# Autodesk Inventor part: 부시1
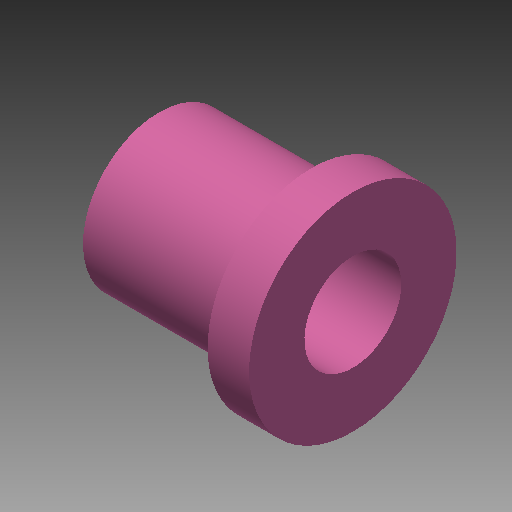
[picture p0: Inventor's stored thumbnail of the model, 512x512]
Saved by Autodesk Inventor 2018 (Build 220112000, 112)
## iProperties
Created: 2020-03
Part Number: 부시1
Material: 스테인리스강
Document SubType Name: Modeling
Designer: mduedu
Density: 8.08 g/cm^3
Appearance: 분홍색
Mass: 8.37674 g
Surface Area: 11.0584 cm^2
Volume: 1.03673 cm^3
Author: mduedu
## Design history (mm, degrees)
sketch "스케치1"
  geometry: L1 (0, 0)-(11, 0); L2 (11, 0)-(11, 5.5); L3 (11, 5.5)-(0, 5.5); L4 (0, 5.5)-(0, 0); L5 (11, 0)-(14, 0); L6 (14, 0)-(14, 7.5); L7 (14, 7.5)-(11, 7.5); L8 (11, 7.5)-(11, 0)
  constraints: 16 end point, 4 parallel, 2 horizontal, 2 perpendicular
  dimensions: "d0" = 14 distance between parallel lines of L6 L4; "d2" = 11 diameter of L3 L1; "d3" = 15 diameter of L7 L5; "d4" = 3 distance of L6.end L7.end
revolve "회전1" sketch "스케치1" stored, may be unused: angle "d5" = 90 deg
hole "구멍1" diameter "d8" = 7; stored, may be unused: countersink angle "d12" = 90 deg, drill point angle "d14" = 118 deg; dims "d6" = 10, "d7" = 10, "d9" = 6, "d10" = 4, "d11" = 2, "d13" = 8
node "솔리드1"
